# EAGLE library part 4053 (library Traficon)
Triple 2-channel ANALOG MULTIPLEXER
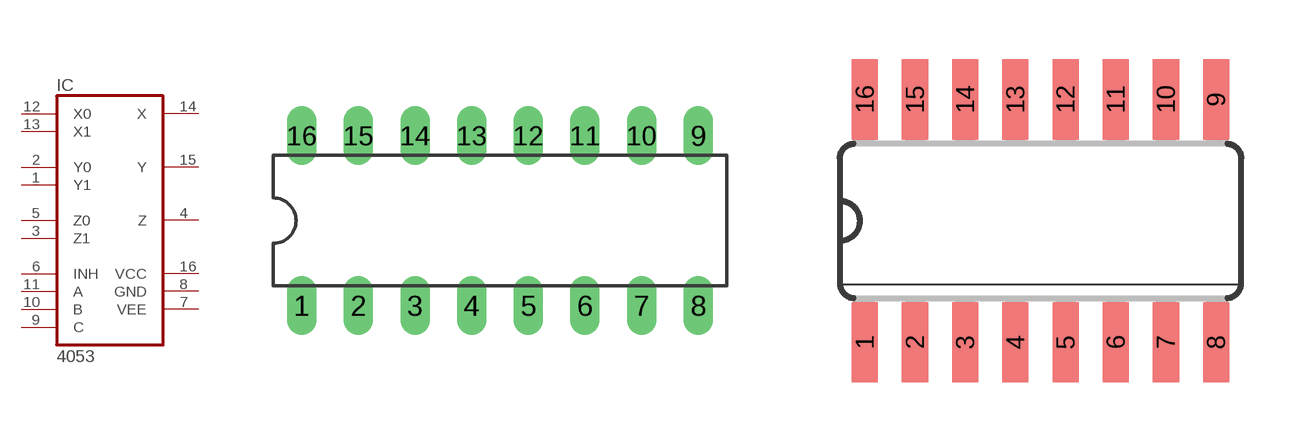
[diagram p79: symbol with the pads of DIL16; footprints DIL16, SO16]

Designator prefix IC

## 4053N  [DIL16]
1  Y1
2  Y0
3  Z1
4  Z
5  Z0
6  INH  in
7  VEE
8  GND
9  C  in
10  B  in
11  A  in
12  X0
13  X1
14  X
15  Y
16  VCC

## 4053D  [SO16]
Pads as for DIL16

## Footprint DIL16 (pad centres in mm)
Dual In Line Package
drill 0.813 long: 1 -8.89,-3.81; 2 -6.35,-3.81; 3 -3.81,-3.81; 4 -1.27,-3.81; 5 1.27,-3.81; 6 3.81,-3.81; 7 6.35,-3.81; 8 8.89,-3.81; 9 8.89,3.81; 10 6.35,3.81; 11 3.81,3.81; 12 1.27,3.81; 13 -1.27,3.81; 14 -3.81,3.81; 15 -6.35,3.81; 16 -8.89,3.81

## Footprint SO16 (pad centres in mm)
Small Outline package 150 mil
smd 0.66 x 2.032: 1 -4.445,-3.073; 2 -3.175,-3.073; 3 -1.905,-3.073; 4 -0.635,-3.073; 5 0.635,-3.073; 6 1.905,-3.073; 7 3.175,-3.073; 8 4.445,-3.073; 9 4.445,3.073; 10 3.175,3.073; 11 1.905,3.073; 12 0.635,3.073; 13 -0.635,3.073; 14 -1.905,3.073; 15 -3.175,3.073; 16 -4.445,3.073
